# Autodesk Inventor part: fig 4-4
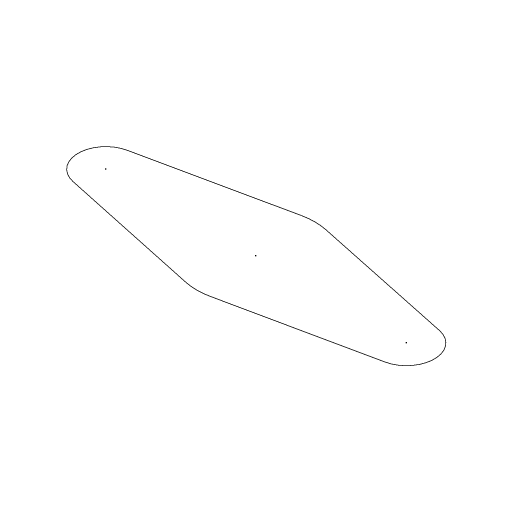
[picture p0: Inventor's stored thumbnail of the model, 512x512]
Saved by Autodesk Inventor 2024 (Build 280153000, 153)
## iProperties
Created: 2005-02
Part Number: fig 4-4
Document SubType Name: Modeling
Designer: CADCIM
Manufacturer: Standard
Standards Organization: Custom
Density: 1 g/cm^3
Material: Generic
Appearance: Default
Author: CADCIM
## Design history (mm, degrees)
sketch "Sketch1"
  geometry: L1 (-33.874, 5.844)-(-2.722, 12.469); L2 (2.595, 12.472)-(33.871, 5.852); L3 (-33.884, -5.902)-(-2.745, -12.585); L4 (2.595, -12.592)-(33.871, -5.972); A1 r 6.006 centre (-32.624, -0.03) between (-33.874, 5.844) and (-33.884, -5.902); A2 r 6.043 centre (32.619, -0.06) between (33.871, -5.972) and (33.871, 5.852); A3 r 12.81 centre (-0.057, -0.06) between (-2.745, -12.585) and (2.595, -12.592); A4 r 12.81 centre (-0.057, -0.06) between (2.595, 12.472) and (-2.722, 12.469)
  constraints: 8 end point, 8 point on circle, 8 tangent, 4 centre point, 1 other
